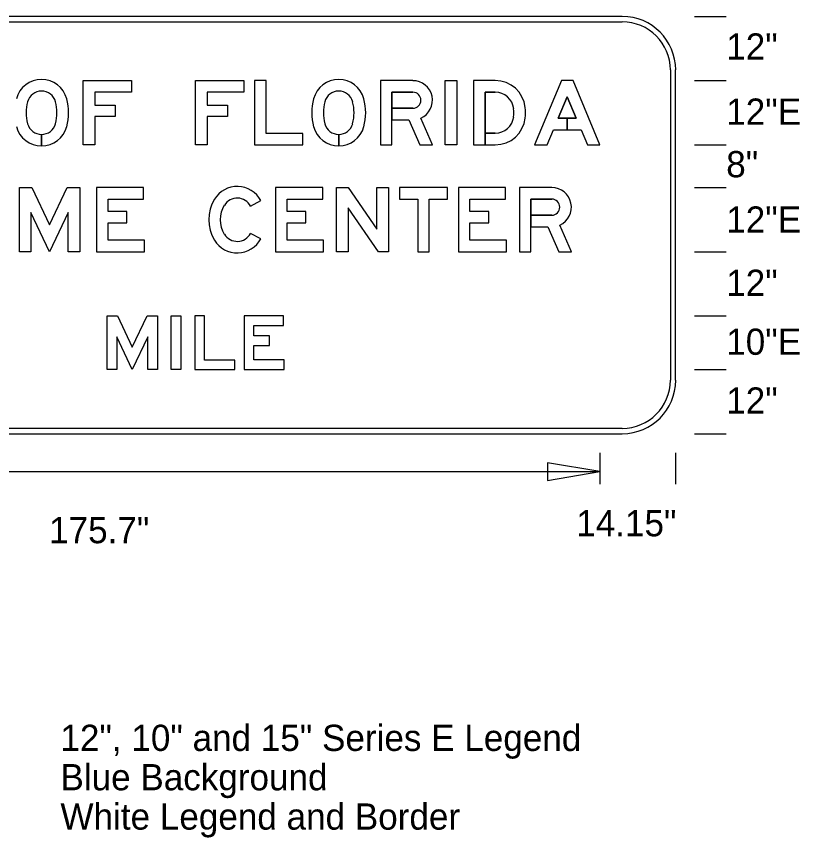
# Model space of a CAD drawing. Extents: x 0 to 770, y 0 to 495.
# Drawn here: x 658.5 to 763, y 11 to 120.6 of the extents above; entities that cross this region are included whole.
import ezdxf

# ---------------------------------------------------------------- set-up
doc = ezdxf.new("R2010")
doc.units = 0
for name, color, linetype in [('Dimension', 7, 'Continuous'), ('GSBWFill', 7, 'Continuous'), ('GSColorFill', 7, 'Continuous'), ('GSDims', 7, 'Continuous'), ('GSOutline', 7, 'Continuous'), ('TextStructures', 7, 'Continuous')]:
    doc.layers.add(name, color=color, linetype=linetype)

msp = doc.modelspace()

# ---------------------------------------------------------------- linework, layer by layer
at = {"layer": 'Dimension'}
msp.add_lwpolyline([(736.39, 59.86), (729.37, 61.05), (729.37, 58.67)], close=True, dxfattribs=at)
at = {"layer": 'GSBWFill'}
for p, q in [((739.36, 120.6), (608.01, 120.6)), ((739.36, 120.6), (608.01, 120.6)), ((608.01, 119.89), (739.36, 119.89)), ((745.78, 113.46), (745.78, 72.06)), ((746.49, 72.06), (746.49, 113.46)), ((746.49, 72.06), (746.49, 113.46)), ((661.86, 103.32), (661.86, 104.86)), ((661.86, 104.86), (661.86, 103.32)), ((701.52, 103.32), (701.52, 104.86)), ((701.52, 104.86), (701.52, 103.32)), ((721.05, 103.47), (722.41, 103.47)), ((689.75, 95.3), (691.11, 96.03)), ((691.11, 90.93), (689.75, 91.65)), ((689.75, 91.65), (689.75, 91.65)), ((739.36, 65.64), (608.01, 65.64)), ((608.01, 64.92), (739.36, 64.92)), ((608.01, 64.92), (739.36, 64.92))]:
    msp.add_line(p, q, dxfattribs=at)
for points in [[(668.97, 107.24), (668.97, 103.47), (667.43, 103.47), (667.43, 112.04), (673.85, 112.04), (673.85, 110.5), (668.97, 110.5), (668.97, 108.78), (671.67, 108.78), (671.67, 107.24)], [(683.96, 107.24), (683.96, 103.47), (682.42, 103.47), (682.42, 112.04), (688.84, 112.04), (688.84, 110.5), (683.96, 110.5), (683.96, 108.78), (686.66, 108.78), (686.66, 107.24)], [(696.72, 103.47), (696.72, 104.97), (691.84, 104.97), (691.84, 112.04), (690.3, 112.04), (690.3, 103.47)], [(715.74, 103.47), (715.74, 112.04), (717.28, 112.04), (717.28, 103.47)], [(733.22, 107.03), (732.02, 107.03), (732.02, 105.48), (733.87, 105.48), (734.71, 103.47), (736.39, 103.47), (732.79, 112.04), (731.25, 112.04), (727.65, 103.47), (729.32, 103.47), (730.17, 105.48), (732.02, 105.48), (732.02, 107.03), (730.81, 107.03), (732.02, 109.89)], [(662.93, 92.78), (665.3, 97.76), (666.96, 97.76), (666.96, 89.19), (665.41, 89.19), (665.41, 94.42), (662.93, 89.19), (660.45, 94.42), (660.45, 89.19), (658.9, 89.19), (658.9, 97.76), (660.57, 97.76)], [(675.61, 90.74), (670.73, 90.74), (670.73, 93.04), (673.25, 93.04), (673.25, 94.58), (670.73, 94.58), (670.73, 96.22), (675.48, 96.22), (675.48, 97.76), (669.18, 97.76), (669.18, 89.19), (675.61, 89.19)], [(699.51, 90.74), (694.63, 90.74), (694.63, 93.04), (697.15, 93.04), (697.15, 94.58), (694.63, 94.58), (694.63, 96.22), (699.38, 96.22), (699.38, 97.76), (693.08, 97.76), (693.08, 89.19), (699.51, 89.19)], [(708.16, 97.76), (708.16, 89.19), (706.83, 89.19), (702.76, 95.06), (702.76, 89.19), (701.22, 89.19), (701.22, 97.76), (702.77, 97.76), (706.62, 92.21), (706.62, 97.76)], [(709.62, 96.22), (712.06, 96.22), (712.06, 89.19), (713.6, 89.19), (713.6, 96.22), (716.04, 96.22), (716.04, 97.76), (709.62, 97.76)], [(723.92, 90.74), (719.04, 90.74), (719.04, 93.04), (721.57, 93.04), (721.57, 94.58), (719.04, 94.58), (719.04, 96.22), (723.79, 96.22), (723.79, 97.76), (717.5, 97.76), (717.5, 89.19), (723.92, 89.19)], [(673.97, 76.48), (675.94, 80.63), (677.32, 80.63), (677.32, 73.49), (676.04, 73.49), (676.04, 77.84), (673.97, 73.49), (671.9, 77.84), (671.9, 73.49), (670.61, 73.49), (670.61, 80.63), (672, 80.63)], [(679.18, 73.49), (679.18, 80.63), (680.46, 80.63), (680.46, 73.49)], [(687.67, 73.49), (687.67, 74.74), (683.6, 74.74), (683.6, 80.63), (682.32, 80.63), (682.32, 73.49)], [(694.24, 74.77), (690.17, 74.77), (690.17, 76.69), (692.28, 76.69), (692.28, 77.98), (690.17, 77.98), (690.17, 79.34), (694.13, 79.34), (694.13, 80.63), (688.89, 80.63), (688.89, 73.49), (694.24, 73.49)]]:
    msp.add_lwpolyline(points, close=True, dxfattribs=at)
for points in [[(711.42, 112.04), (707.09, 112.04), (707.09, 103.47), (708.63, 103.47), (708.63, 110.5), (711.42, 110.5)], [(722.41, 112.04), (719.51, 112.04), (719.51, 103.47), (721.05, 103.47), (721.05, 110.5), (722.41, 110.5)], [(711.42, 108.35), (708.63, 108.35), (708.63, 106.81)], [(708.63, 106.81), (710.9, 106.81), (712.35, 103.47), (714.03, 103.47), (712.48, 107.04)], [(722.41, 105.01), (721.05, 105.01), (721.05, 103.47)], [(729.96, 97.76), (725.64, 97.76), (725.64, 89.19), (727.18, 89.19), (727.18, 96.22), (729.96, 96.22)], [(729.96, 94.08), (727.18, 94.08), (727.18, 92.53)], [(727.18, 92.53), (729.45, 92.53), (730.89, 89.19), (732.57, 89.19), (731.03, 92.76)]]:
    msp.add_lwpolyline(points, dxfattribs=at)
for centre, radius, start, end in [((739.36, 113.46), 7.14, 0, 90), ((739.36, 113.46), 7.14, 0, 90), ((739.36, 113.46), 6.42, 0, 90), ((661.86, 108.72), 3.47, 14.9618, 165.0382), ((661.86, 108.72), 1.93, 14.9618, 165.0382), ((658.26, 107.75), 7.2, 345.0382, 14.9618), ((665.46, 107.75), 5.65, 165.0382, 194.9618), ((658.26, 107.75), 5.65, 345.0382, 14.9618), ((661.86, 106.79), 1.93, 194.9618, 270), ((661.86, 106.79), 1.93, 270.0127, 345.0382), ((661.86, 106.79), 3.47, 194.9618, 270), ((661.86, 106.79), 3.47, 270.0071, 345.0382), ((739.36, 72.06), 7.14, 270, 0), ((739.36, 72.06), 6.42, 270, 0), ((739.36, 72.06), 7.14, 270, 0)]:
    msp.add_arc(centre, radius, start, end, dxfattribs=at)
for centre, major_axis, start_param, end_param in [((701.52, 108.72), (0, 3.47), 4.973521, 7.592849), ((711.42, 109.42), (0, 2.61), 3.562504, 6.283185), ((722.41, 108.01), (0, 4.03), 4.82584, 6.283185), ((705.12, 107.75), (0, 7.2), 1.309664, 1.831929), ((701.52, 108.72), (0, 1.93), 4.973521, 7.592849), ((697.92, 107.75), (0, 7.2), 4.451257, 4.973521), ((711.42, 109.42), (0, 1.07), 3.141593, 6.283185), ((722.41, 108.01), (0, 2.48), 4.82584, 6.283185), ((705.12, 107.75), (0, 5.65), 1.309664, 1.831929), ((697.92, 107.75), (0, 5.65), 4.451257, 4.973521), ((720.15, 107.75), (0, 4.75), 4.598938, 4.82584), ((720.15, 107.75), (0, 6.3), 4.598938, 4.82584), ((701.52, 106.79), (0, 1.93), 1.831929, 3.141593), ((701.52, 106.79), (0, 1.93), 3.141815, 4.451257), ((722.41, 107.5), (0, 2.48), 3.141593, 4.598938), ((722.41, 107.5), (0, 4.03), 3.141593, 4.598938), ((701.52, 106.79), (0, 3.47), 1.831929, 3.141593), ((701.52, 106.79), (0, 3.47), 3.141716, 4.451257), ((687.98, 94.35), (0, 3.56), 5.201543, 7.308565), ((729.96, 95.15), (0, 2.61), 3.562504, 6.283185), ((689.42, 93.48), (0, 5.25), 1.025379, 2.116213), ((689.42, 93.48), (0, 3.71), 1.025379, 2.116213), ((687.98, 94.35), (0, 2.01), 5.201543, 7.308565), ((729.96, 95.15), (0, 1.07), 3.141593, 6.283185), ((687.98, 92.6), (0, 2.01), 2.116213, 4.223235), ((687.98, 92.6), (0, 3.56), 2.116213, 4.223235)]:
    msp.add_ellipse(centre, major_axis=major_axis, ratio=0.999994, start_param=start_param, end_param=end_param, dxfattribs=at)
at = {"layer": 'GSColorFill'}
for p, q in [((661.86, 103.32), (661.86, 104.86)), ((661.86, 104.86), (661.86, 103.32)), ((701.52, 103.32), (701.52, 104.86)), ((701.52, 104.86), (701.52, 103.32)), ((721.05, 103.47), (722.41, 103.47)), ((689.75, 95.3), (691.11, 96.03)), ((691.11, 90.93), (689.75, 91.65)), ((689.75, 91.65), (689.75, 91.65))]:
    msp.add_line(p, q, dxfattribs=at)
for points in [[(668.97, 107.24), (668.97, 103.47), (667.43, 103.47), (667.43, 112.04), (673.85, 112.04), (673.85, 110.5), (668.97, 110.5), (668.97, 108.78), (671.67, 108.78), (671.67, 107.24)], [(683.96, 107.24), (683.96, 103.47), (682.42, 103.47), (682.42, 112.04), (688.84, 112.04), (688.84, 110.5), (683.96, 110.5), (683.96, 108.78), (686.66, 108.78), (686.66, 107.24)], [(696.72, 103.47), (696.72, 104.97), (691.84, 104.97), (691.84, 112.04), (690.3, 112.04), (690.3, 103.47)], [(715.74, 103.47), (715.74, 112.04), (717.28, 112.04), (717.28, 103.47)], [(733.22, 107.03), (732.02, 107.03), (732.02, 105.48), (733.87, 105.48), (734.71, 103.47), (736.39, 103.47), (732.79, 112.04), (731.25, 112.04), (727.65, 103.47), (729.32, 103.47), (730.17, 105.48), (732.02, 105.48), (732.02, 107.03), (730.81, 107.03), (732.02, 109.89)], [(662.93, 92.78), (665.3, 97.76), (666.96, 97.76), (666.96, 89.19), (665.41, 89.19), (665.41, 94.42), (662.93, 89.19), (660.45, 94.42), (660.45, 89.19), (658.9, 89.19), (658.9, 97.76), (660.57, 97.76)], [(675.61, 90.74), (670.73, 90.74), (670.73, 93.04), (673.25, 93.04), (673.25, 94.58), (670.73, 94.58), (670.73, 96.22), (675.48, 96.22), (675.48, 97.76), (669.18, 97.76), (669.18, 89.19), (675.61, 89.19)], [(699.51, 90.74), (694.63, 90.74), (694.63, 93.04), (697.15, 93.04), (697.15, 94.58), (694.63, 94.58), (694.63, 96.22), (699.38, 96.22), (699.38, 97.76), (693.08, 97.76), (693.08, 89.19), (699.51, 89.19)], [(708.16, 97.76), (708.16, 89.19), (706.83, 89.19), (702.76, 95.06), (702.76, 89.19), (701.22, 89.19), (701.22, 97.76), (702.77, 97.76), (706.62, 92.21), (706.62, 97.76)], [(709.62, 96.22), (712.06, 96.22), (712.06, 89.19), (713.6, 89.19), (713.6, 96.22), (716.04, 96.22), (716.04, 97.76), (709.62, 97.76)], [(723.92, 90.74), (719.04, 90.74), (719.04, 93.04), (721.57, 93.04), (721.57, 94.58), (719.04, 94.58), (719.04, 96.22), (723.79, 96.22), (723.79, 97.76), (717.5, 97.76), (717.5, 89.19), (723.92, 89.19)], [(673.97, 76.48), (675.94, 80.63), (677.32, 80.63), (677.32, 73.49), (676.04, 73.49), (676.04, 77.84), (673.97, 73.49), (671.9, 77.84), (671.9, 73.49), (670.61, 73.49), (670.61, 80.63), (672, 80.63)], [(679.18, 73.49), (679.18, 80.63), (680.46, 80.63), (680.46, 73.49)], [(687.67, 73.49), (687.67, 74.74), (683.6, 74.74), (683.6, 80.63), (682.32, 80.63), (682.32, 73.49)], [(694.24, 74.77), (690.17, 74.77), (690.17, 76.69), (692.28, 76.69), (692.28, 77.98), (690.17, 77.98), (690.17, 79.34), (694.13, 79.34), (694.13, 80.63), (688.89, 80.63), (688.89, 73.49), (694.24, 73.49)]]:
    msp.add_lwpolyline(points, close=True, dxfattribs=at)
for points in [[(711.42, 112.04), (707.09, 112.04), (707.09, 103.47), (708.63, 103.47), (708.63, 110.5), (711.42, 110.5)], [(722.41, 112.04), (719.51, 112.04), (719.51, 103.47), (721.05, 103.47), (721.05, 110.5), (722.41, 110.5)], [(711.42, 108.35), (708.63, 108.35), (708.63, 106.81)], [(708.63, 106.81), (710.9, 106.81), (712.35, 103.47), (714.03, 103.47), (712.48, 107.04)], [(722.41, 105.01), (721.05, 105.01), (721.05, 103.47)], [(729.96, 97.76), (725.64, 97.76), (725.64, 89.19), (727.18, 89.19), (727.18, 96.22), (729.96, 96.22)], [(729.96, 94.08), (727.18, 94.08), (727.18, 92.53)], [(727.18, 92.53), (729.45, 92.53), (730.89, 89.19), (732.57, 89.19), (731.03, 92.76)]]:
    msp.add_lwpolyline(points, dxfattribs=at)
for centre, radius, start, end in [((661.86, 108.72), 3.47, 14.9618, 165.0382), ((661.86, 108.72), 1.93, 14.9618, 165.0382), ((658.26, 107.75), 7.2, 345.0382, 14.9618), ((665.46, 107.75), 5.65, 165.0382, 194.9618), ((658.26, 107.75), 5.65, 345.0382, 14.9618), ((661.86, 106.79), 1.93, 194.9618, 270), ((661.86, 106.79), 1.93, 270.0127, 345.0382), ((661.86, 106.79), 3.47, 194.9618, 270), ((661.86, 106.79), 3.47, 270.0071, 345.0382)]:
    msp.add_arc(centre, radius, start, end, dxfattribs=at)
for centre, major_axis, start_param, end_param in [((701.52, 108.72), (0, 3.47), 4.973521, 7.592849), ((711.42, 109.42), (0, 2.61), 3.562504, 6.283185), ((722.41, 108.01), (0, 4.03), 4.82584, 6.283185), ((705.12, 107.75), (0, 7.2), 1.309664, 1.831929), ((701.52, 108.72), (0, 1.93), 4.973521, 7.592849), ((697.92, 107.75), (0, 7.2), 4.451257, 4.973521), ((711.42, 109.42), (0, 1.07), 3.141593, 6.283185), ((722.41, 108.01), (0, 2.48), 4.82584, 6.283185), ((705.12, 107.75), (0, 5.65), 1.309664, 1.831929), ((697.92, 107.75), (0, 5.65), 4.451257, 4.973521), ((720.15, 107.75), (0, 4.75), 4.598938, 4.82584), ((720.15, 107.75), (0, 6.3), 4.598938, 4.82584), ((701.52, 106.79), (0, 1.93), 1.831929, 3.141593), ((701.52, 106.79), (0, 1.93), 3.141815, 4.451257), ((722.41, 107.5), (0, 2.48), 3.141593, 4.598938), ((722.41, 107.5), (0, 4.03), 3.141593, 4.598938), ((701.52, 106.79), (0, 3.47), 1.831929, 3.141593), ((701.52, 106.79), (0, 3.47), 3.141716, 4.451257), ((687.98, 94.35), (0, 3.56), 5.201543, 7.308565), ((729.96, 95.15), (0, 2.61), 3.562504, 6.283185), ((689.42, 93.48), (0, 5.25), 1.025379, 2.116213), ((689.42, 93.48), (0, 3.71), 1.025379, 2.116213), ((687.98, 94.35), (0, 2.01), 5.201543, 7.308565), ((729.96, 95.15), (0, 1.07), 3.141593, 6.283185), ((687.98, 92.6), (0, 2.01), 2.116213, 4.223235), ((687.98, 92.6), (0, 3.56), 2.116213, 4.223235)]:
    msp.add_ellipse(centre, major_axis=major_axis, ratio=0.999994, start_param=start_param, end_param=end_param, dxfattribs=at)
at = {"layer": 'GSDims'}
for p, q in [((749.02, 120.6), (753.24, 120.6)), ((749.02, 112.04), (753.24, 112.04)), ((749.02, 112.04), (753.24, 112.04)), ((749.02, 103.47), (753.24, 103.47)), ((749.02, 103.47), (753.24, 103.47)), ((749.02, 97.76), (753.24, 97.76)), ((749.02, 97.76), (753.24, 97.76)), ((749.02, 89.19), (753.24, 89.19)), ((749.02, 89.19), (753.24, 89.19)), ((749.02, 80.63), (753.24, 80.63)), ((749.02, 80.63), (753.24, 80.63)), ((749.02, 73.49), (753.24, 73.49)), ((749.02, 73.49), (753.24, 73.49)), ((749.02, 64.92), (753.24, 64.92)), ((736.39, 62.39), (736.39, 58.18)), ((736.39, 62.39), (736.39, 58.18)), ((746.49, 62.39), (746.49, 58.18)), ((610.98, 59.86), (736.39, 59.86))]:
    msp.add_line(p, q, dxfattribs=at)
at = {"layer": 'GSOutline'}
for p, q in [((708.63, 108.35), (711.42, 108.35)), ((721.05, 105.01), (722.41, 105.01)), ((689.75, 95.3), (691.11, 96.03)), ((727.18, 94.08), (729.96, 94.08)), ((691.11, 90.93), (689.75, 91.65)), ((689.75, 91.65), (689.75, 91.65))]:
    msp.add_line(p, q, dxfattribs=at)
for points in [[(668.97, 107.24), (668.97, 103.47), (667.43, 103.47), (667.43, 112.04), (673.85, 112.04), (673.85, 110.5), (668.97, 110.5), (668.97, 108.78), (671.67, 108.78), (671.67, 107.24)], [(683.96, 107.24), (683.96, 103.47), (682.42, 103.47), (682.42, 112.04), (688.84, 112.04), (688.84, 110.5), (683.96, 110.5), (683.96, 108.78), (686.66, 108.78), (686.66, 107.24)], [(696.72, 103.47), (696.72, 104.97), (691.84, 104.97), (691.84, 112.04), (690.3, 112.04), (690.3, 103.47)], [(715.74, 103.47), (715.74, 112.04), (717.28, 112.04), (717.28, 103.47)], [(730.17, 105.48), (733.87, 105.48), (734.71, 103.47), (736.39, 103.47), (732.79, 112.04), (731.25, 112.04), (727.65, 103.47), (729.32, 103.47)], [(733.22, 107.03), (732.02, 109.89), (730.81, 107.03)], [(662.93, 92.78), (665.3, 97.76), (666.96, 97.76), (666.96, 89.19), (665.41, 89.19), (665.41, 94.42), (662.93, 89.19), (660.45, 94.42), (660.45, 89.19), (658.9, 89.19), (658.9, 97.76), (660.57, 97.76)], [(675.61, 90.74), (670.73, 90.74), (670.73, 93.04), (673.25, 93.04), (673.25, 94.58), (670.73, 94.58), (670.73, 96.22), (675.48, 96.22), (675.48, 97.76), (669.18, 97.76), (669.18, 89.19), (675.61, 89.19)], [(699.51, 90.74), (694.63, 90.74), (694.63, 93.04), (697.15, 93.04), (697.15, 94.58), (694.63, 94.58), (694.63, 96.22), (699.38, 96.22), (699.38, 97.76), (693.08, 97.76), (693.08, 89.19), (699.51, 89.19)], [(708.16, 97.76), (708.16, 89.19), (706.83, 89.19), (702.76, 95.06), (702.76, 89.19), (701.22, 89.19), (701.22, 97.76), (702.77, 97.76), (706.62, 92.21), (706.62, 97.76)], [(709.62, 96.22), (712.06, 96.22), (712.06, 89.19), (713.6, 89.19), (713.6, 96.22), (716.04, 96.22), (716.04, 97.76), (709.62, 97.76)], [(723.92, 90.74), (719.04, 90.74), (719.04, 93.04), (721.57, 93.04), (721.57, 94.58), (719.04, 94.58), (719.04, 96.22), (723.79, 96.22), (723.79, 97.76), (717.5, 97.76), (717.5, 89.19), (723.92, 89.19)], [(673.97, 76.48), (675.94, 80.63), (677.32, 80.63), (677.32, 73.49), (676.04, 73.49), (676.04, 77.84), (673.97, 73.49), (671.9, 77.84), (671.9, 73.49), (670.61, 73.49), (670.61, 80.63), (672, 80.63)], [(679.18, 73.49), (679.18, 80.63), (680.46, 80.63), (680.46, 73.49)], [(687.67, 73.49), (687.67, 74.74), (683.6, 74.74), (683.6, 80.63), (682.32, 80.63), (682.32, 73.49)], [(694.24, 74.77), (690.17, 74.77), (690.17, 76.69), (692.28, 76.69), (692.28, 77.98), (690.17, 77.98), (690.17, 79.34), (694.13, 79.34), (694.13, 80.63), (688.89, 80.63), (688.89, 73.49), (694.24, 73.49)]]:
    msp.add_lwpolyline(points, close=True, dxfattribs=at)
for points in [[(711.42, 112.04), (707.09, 112.04), (707.09, 103.47), (708.63, 103.47), (708.63, 106.81), (710.9, 106.81)], [(722.41, 112.04), (719.51, 112.04), (719.51, 103.47), (722.41, 103.47)], [(711.42, 110.5), (708.63, 110.5), (708.63, 108.35)], [(722.41, 110.5), (721.05, 110.5), (721.05, 105.01)], [(710.9, 106.81), (712.35, 103.47), (714.03, 103.47), (712.48, 107.04)], [(729.96, 97.76), (725.64, 97.76), (725.64, 89.19), (727.18, 89.19), (727.18, 92.53), (729.45, 92.53)], [(729.96, 96.22), (727.18, 96.22), (727.18, 94.08)], [(729.45, 92.53), (730.89, 89.19), (732.57, 89.19), (731.03, 92.76)]]:
    msp.add_lwpolyline(points, dxfattribs=at)
for centre, radius, start, end in [((661.86, 108.72), 3.47, 14.9618, 165.0382), ((661.86, 108.72), 1.93, 14.9618, 165.0382), ((658.26, 107.75), 7.2, 345.0382, 14.9618), ((665.46, 107.75), 5.65, 165.0382, 194.9618), ((658.26, 107.75), 5.65, 345.0382, 14.9618), ((661.86, 106.79), 1.93, 194.9618, 345.0382), ((661.86, 106.79), 3.47, 194.9618, 345.0382)]:
    msp.add_arc(centre, radius, start, end, dxfattribs=at)
for centre, major_axis, start_param, end_param in [((701.52, 108.72), (0, 3.47), 4.973521, 7.592849), ((711.42, 109.42), (0, 2.61), 3.562504, 6.283185), ((722.41, 108.01), (0, 4.03), 4.82584, 6.283185), ((705.12, 107.75), (0, 7.2), 1.309664, 1.831929), ((701.52, 108.72), (0, 1.93), 4.973521, 7.592849), ((697.92, 107.75), (0, 7.2), 4.451257, 4.973521), ((711.42, 109.42), (0, 1.07), 3.141593, 6.283185), ((722.41, 108.01), (0, 2.48), 4.82584, 6.283185), ((705.12, 107.75), (0, 5.65), 1.309664, 1.831929), ((697.92, 107.75), (0, 5.65), 4.451257, 4.973521), ((720.15, 107.75), (0, 4.75), 4.598938, 4.82584), ((720.15, 107.75), (0, 6.3), 4.598938, 4.82584), ((701.52, 106.79), (0, 1.93), 1.831929, 4.451257), ((722.41, 107.5), (0, 2.48), 3.141593, 4.598938), ((722.41, 107.5), (0, 4.03), 3.141593, 4.598938), ((701.52, 106.79), (0, 3.47), 1.831929, 4.451257), ((687.98, 94.35), (0, 3.56), 5.201543, 7.308565), ((729.96, 95.15), (0, 2.61), 3.562504, 6.283185), ((689.42, 93.48), (0, 5.25), 1.025379, 2.116213), ((689.42, 93.48), (0, 3.71), 1.025379, 2.116213), ((687.98, 94.35), (0, 2.01), 5.201543, 7.308565), ((729.96, 95.15), (0, 1.07), 3.141593, 6.283185), ((687.98, 92.6), (0, 2.01), 2.116213, 4.223235), ((687.98, 92.6), (0, 3.56), 2.116213, 4.223235)]:
    msp.add_ellipse(centre, major_axis=major_axis, ratio=0.999994, start_param=start_param, end_param=end_param, dxfattribs=at)

# ---------------------------------------------------------------- texts
at = {"layer": 'TextStructures'}
for s, p in [('12"', (753.24, 114.84)), ('12"E', (753.24, 106.15)), ('8"', (753.24, 99.14)), ('12"E', (753.24, 91.75)), ('12"', (753.24, 83.31)), ('10"E', (753.24, 75.45)), ('12"', (753.24, 67.6)), ('175.7"', (662.87, 50.31)), ('14.15"', (733.22, 51.23)), ('12", 10" and 15" Series E Legend', (664.38, 22.59)), ('Blue Background', (664.38, 17.34)), ('White Legend and Border', (664.38, 12.09))]:
    msp.add_text(s, height=3.5, dxfattribs=at).set_placement(p)

doc.saveas('drawing.dxf')
